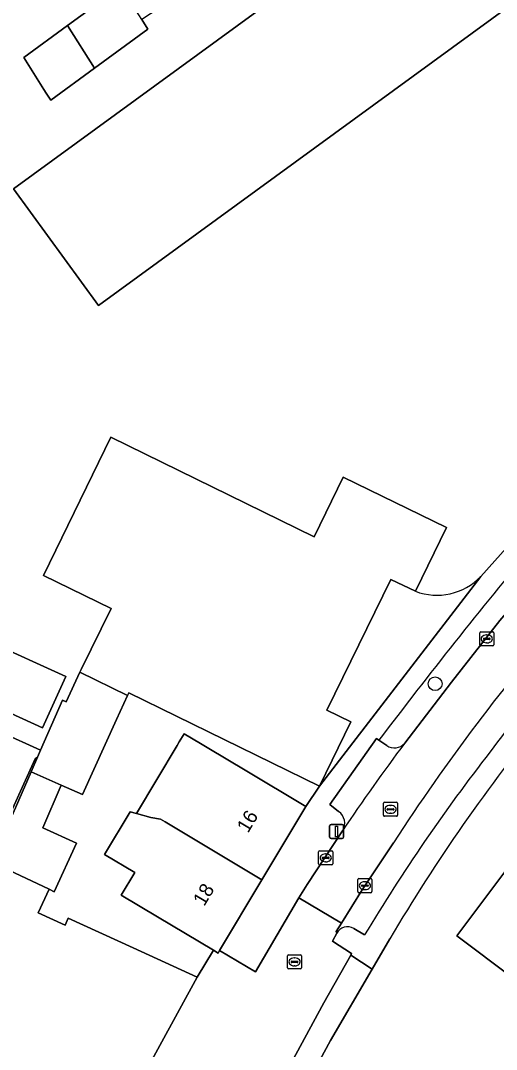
# Model space of a CAD drawing. Extents: x 161881 to 162523, y 381678 to 382381.
# Drawn here: x 162276 to 162309.8, y 381824.1 to 381897.2 of the extents above; entities that cross this region are included whole.
import ezdxf

# ---------------------------------------------------------------- set-up
doc = ezdxf.new("R2010")
doc.units = 0
for name, color, linetype in [('IMGEO_Boom', 7, 'Continuous'), ('IMGEO_Erf', 7, 'Continuous'), ('IMGEO_Groenvoorziening', 7, 'Continuous'), ('IMGEO_Kolk', 7, 'Continuous'), ('IMGEO_Lichtmast', 7, 'Continuous'), ('IMGEO_Muur', 7, 'Continuous'), ('IMGEO_Pand', 7, 'Continuous'), ('IMGEO_Pand_nummerreeks', 7, 'Continuous'), ('IMGEO_Parkeervlak_open', 7, 'Continuous'), ('IMGEO_Rijbaan_lokaal_open', 7, 'Continuous'), ('IMGEO_Rioolput', 7, 'Continuous'), ('IMGEO_Voetpad_open', 7, 'Continuous')]:
    doc.layers.add(name, color=color, linetype=linetype)

msp = doc.modelspace()

# ---------------------------------------------------------------- linework, layer by layer
at = {"layer": 'IMGEO_Boom'}
msp.add_circle((162305.454, 381850.04), 0.489, dxfattribs=at)
at = {"layer": 'IMGEO_Erf'}
for points in [[(162275.507, 381885.197), (162313.123, 381912.663)], [(162308.695, 381857.661), (162317.651, 381867.68), (162320.093, 381870.515), (162317.508, 381873.557), (162311.416, 381880.988), (162315.774, 381884.648), (162315.994, 381884.379), (162316.488, 381884.836), (162316.601, 381884.938), (162316.382, 381885.179), (162318.764, 381887.154), (162318.965, 381886.995), (162319.543, 381887.466), (162319.343, 381887.695), (162320.508, 381888.575), (162315.645, 381894.334), (162318.477, 381896.725), (162315.068, 381901.394), (162281.55, 381876.921), (162275.507, 381885.197)], [(162274.603, 381846.604), (162277.429, 381845.321), (162278.983, 381848.869), (162279.241, 381848.751), (162280.22, 381850.86), (162280.31, 381851.043), (162282.429, 381855.385), (162277.623, 381857.736), (162282.425, 381867.55), (162296.856, 381860.49), (162298.927, 381864.723), (162306.263, 381861.133), (162304.05, 381856.609)], [(162273.937, 381837.352), (162276.749, 381843.77), (162277.212, 381844.825), (162277.045, 381844.695), (162273.678, 381837.331)], [(162302.232, 381831.916), (162300.971, 381829.755), (162298.019, 381824.698), (162294.798, 381818.75)]]:
    msp.add_lwpolyline(points, dxfattribs=at)
for points in [[(162278.151, 381891.503), (162277.827, 381892.015), (162277.662, 381892.277), (162276.229, 381894.543), (162279.326, 381896.811), (162283.128, 381899.595), (162282.478, 381900.624), (162284.502, 381901.961), (162284.785, 381902.148), (162286.788, 381903.471), (162286.974, 381903.176), (162288.926, 381900.089), (162284.616, 381897.241), (162285.049, 381896.555), (162281.247, 381893.771)], [(162279.221, 381850.549), (162277.559, 381846.911), (162272.006, 381849.436), (162273.668, 381853.074)], [(162324.194, 381841.527), (162320.657, 381836.81), (162323.58, 381834.6), (162320.051, 381829.895), (162317.092, 381832.114), (162313.465, 381827.278), (162310.999, 381829.127), (162306.999, 381832.127), (162310.626, 381836.963), (162314.163, 381841.68), (162317.701, 381846.396), (162321.328, 381851.233), (162325.328, 381848.233), (162327.821, 381846.363)], [(162287.133, 381845.652), (162287.282, 381845.902), (162287.63, 381846.483), (162288.786, 381845.792), (162289.388, 381845.432), (162291.968, 381843.889), (162296.259, 381841.323), (162297.241, 381842.76), (162283.693, 381849.389), (162283.607, 381849.201), (162282.828, 381847.495), (162280.399, 381842.176), (162278.877, 381842.841), (162277.585, 381839.797), (162279.968, 381838.708), (162278.395, 381835.263), (162278.028, 381835.435), (162277.263, 381833.76), (162279.176, 381832.887), (162279.396, 381833.371), (162283.992, 381831.27), (162288.539, 381829.192), (162289.703, 381831.102), (162285.739, 381833.472), (162283.159, 381835.015), (162284.124, 381836.63), (162281.972, 381837.916), (162283.782, 381840.944), (162284.241, 381840.816)]]:
    msp.add_lwpolyline(points, close=True, dxfattribs=at)
for centre, radius, start, end in [((162305.575, 381860.656), 4.325, 249.35475, 316.1674), ((162413.302, 381766.264), 129.022, 140.83, 149.413)]:
    msp.add_arc(centre, radius, start, end, dxfattribs=at)
at = {"layer": 'IMGEO_Groenvoorziening'}
for points in [[(162303.292, 381845.82), (162306.611, 381850.151), (162310.057, 381854.543), (162313.959, 381859.114), (162317.095, 381862.667), (162320.649, 381866.638)], [(162301.461, 381846.023), (162302.017, 381845.655)]]:
    msp.add_lwpolyline(points, dxfattribs=at)
msp.add_lwpolyline([(162300.971, 381829.755), (162299.458, 381830.76), (162297.547, 381827.377), (162294.938, 381822.561), (162294.387, 381822.839), (162294.119, 381822.297), (162293.749, 381821.597), (162294.258, 381821.315), (162293.302, 381819.526), (162294.798, 381818.75), (162298.019, 381824.698)], close=True, dxfattribs=at)
for centre, radius, start, end in [((162591.617, 381627.062), 363.503, 140.18045, 142.96062), ((162302.567, 381846.417), 0.94, 234.21404, 320.53349)]:
    msp.add_arc(centre, radius, start, end, dxfattribs=at)
at = {"layer": 'IMGEO_Kolk'}
for p, q in [((162308.622, 381852.803), (162308.622, 381853.655)), ((162308.697, 381853.729), (162309.549, 381853.729)), ((162309.623, 381853.655), (162309.623, 381852.803)), ((162308.881, 381853.223), (162308.881, 381853.235)), ((162309.319, 381853.186), (162308.921, 381853.186)), ((162308.924, 381853.272), (162309.322, 381853.272)), ((162309.133, 381852.949), (162309.108, 381852.949)), ((162309.11, 381853.509), (162309.135, 381853.509)), ((162309.365, 381853.235), (162309.365, 381853.223)), ((162309.549, 381852.729), (162308.697, 381852.729)), ((162297.179, 381837.241), (162297.179, 381838.093)), ((162297.254, 381838.167), (162298.106, 381838.167)), ((162297.438, 381837.661), (162297.438, 381837.673)), ((162297.876, 381837.624), (162297.478, 381837.624)), ((162297.481, 381837.71), (162297.879, 381837.71)), ((162297.667, 381837.947), (162297.692, 381837.947)), ((162297.922, 381837.673), (162297.922, 381837.661)), ((162298.18, 381838.093), (162298.18, 381837.241)), ((162298.106, 381837.167), (162297.254, 381837.167)), ((162297.69, 381837.387), (162297.665, 381837.387)), ((162299.966, 381835.267), (162299.966, 381836.119)), ((162300.041, 381836.193), (162300.893, 381836.193)), ((162300.967, 381836.119), (162300.967, 381835.267)), ((162300.225, 381835.687), (162300.225, 381835.699)), ((162300.663, 381835.65), (162300.265, 381835.65)), ((162300.268, 381835.736), (162300.666, 381835.736)), ((162300.477, 381835.413), (162300.452, 381835.413)), ((162300.454, 381835.973), (162300.479, 381835.973)), ((162300.709, 381835.699), (162300.709, 381835.687)), ((162300.893, 381835.193), (162300.041, 381835.193)), ((162294.966, 381829.85), (162294.966, 381830.702)), ((162295.041, 381830.776), (162295.893, 381830.776)), ((162295.225, 381830.27), (162295.225, 381830.282)), ((162295.268, 381830.319), (162295.666, 381830.319)), ((162295.454, 381830.556), (162295.479, 381830.556)), ((162295.709, 381830.282), (162295.709, 381830.27)), ((162295.967, 381830.702), (162295.967, 381829.85)), ((162295.893, 381829.776), (162295.041, 381829.776)), ((162295.663, 381830.233), (162295.265, 381830.233)), ((162295.477, 381829.996), (162295.452, 381829.996))]:
    msp.add_line(p, q, dxfattribs=at)
for points in [[(162308.622, 381852.803), (162308.622, 381853.655)], [(162308.697, 381853.729), (162309.549, 381853.729)], [(162309.623, 381853.655), (162309.623, 381852.803)], [(162309.549, 381852.729), (162308.697, 381852.729)], [(162297.179, 381837.241), (162297.179, 381838.093)], [(162297.254, 381838.167), (162298.106, 381838.167)], [(162298.18, 381838.093), (162298.18, 381837.241)], [(162298.106, 381837.167), (162297.254, 381837.167)], [(162299.966, 381835.267), (162299.966, 381836.119)], [(162300.041, 381836.193), (162300.893, 381836.193)], [(162300.967, 381836.119), (162300.967, 381835.267)], [(162300.893, 381835.193), (162300.041, 381835.193)], [(162294.966, 381829.85), (162294.966, 381830.702)], [(162295.041, 381830.776), (162295.893, 381830.776)], [(162295.967, 381830.702), (162295.967, 381829.85)], [(162295.893, 381829.776), (162295.041, 381829.776)]]:
    msp.add_lwpolyline(points, dxfattribs=at)
for centre, radius, start, end in [((162308.699, 381853.653), 0.0765, 91.55205, 178.44795), ((162308.699, 381853.653), 0.0765, 91.55205, 178.44795), ((162309.547, 381853.653), 0.0765, 1.55205, 88.44795), ((162309.547, 381853.653), 0.0765, 1.55205, 88.44795), ((162308.921, 381853.232), 0.0403, 85.87752, 175.75265), ((162308.918, 381853.222), 0.0366, 178.93798, 274.71019), ((162309.322, 381853.229), 0.043, 264.86636, 352.45326), ((162309.326, 381853.234), 0.0386, 1.73085, 96.63898), ((162308.699, 381852.805), 0.0765, 181.55205, 268.44795), ((162308.699, 381852.805), 0.0765, 181.55205, 268.44795), ((162309.547, 381852.805), 0.0765, 271.55205, 358.44795), ((162309.547, 381852.805), 0.0765, 271.55205, 358.44795), ((162297.256, 381838.091), 0.0765, 91.55205, 178.44795), ((162297.256, 381838.091), 0.0765, 91.55205, 178.44795), ((162297.478, 381837.67), 0.0403, 85.87752, 175.75265), ((162297.475, 381837.66), 0.0366, 178.93798, 274.71019), ((162297.879, 381837.667), 0.043, 264.86636, 352.45326), ((162297.883, 381837.672), 0.0386, 1.73085, 96.63898), ((162298.104, 381838.091), 0.0765, 1.55205, 88.44795), ((162298.104, 381838.091), 0.0765, 1.55205, 88.44795), ((162297.256, 381837.243), 0.0765, 181.55205, 268.44795), ((162297.256, 381837.243), 0.0765, 181.55205, 268.44795), ((162298.104, 381837.243), 0.0765, 271.55205, 358.44795), ((162298.104, 381837.243), 0.0765, 271.55205, 358.44795), ((162300.043, 381836.117), 0.0765, 91.55205, 178.44795), ((162300.043, 381836.117), 0.0765, 91.55205, 178.44795), ((162300.891, 381836.117), 0.0765, 1.55205, 88.44795), ((162300.891, 381836.117), 0.0765, 1.55205, 88.44795), ((162300.265, 381835.696), 0.0403, 85.87752, 175.75265), ((162300.262, 381835.686), 0.0366, 178.93798, 274.71019), ((162300.666, 381835.693), 0.043, 264.86636, 352.45326), ((162300.67, 381835.698), 0.0386, 1.73085, 96.63898), ((162300.043, 381835.269), 0.0765, 181.55205, 268.44795), ((162300.043, 381835.269), 0.0765, 181.55205, 268.44795), ((162300.891, 381835.269), 0.0765, 271.55205, 358.44795), ((162300.891, 381835.269), 0.0765, 271.55205, 358.44795), ((162295.043, 381830.7), 0.0765, 91.55205, 178.44795), ((162295.043, 381830.7), 0.0765, 91.55205, 178.44795), ((162295.265, 381830.279), 0.0403, 85.87752, 175.75265), ((162295.262, 381830.269), 0.0366, 178.93798, 274.71019), ((162295.666, 381830.276), 0.043, 264.86636, 352.45326), ((162295.67, 381830.281), 0.0386, 1.73085, 96.63898), ((162295.891, 381830.7), 0.0765, 1.55205, 88.44795), ((162295.891, 381830.7), 0.0765, 1.55205, 88.44795), ((162295.043, 381829.852), 0.0765, 181.55205, 268.44795), ((162295.043, 381829.852), 0.0765, 181.55205, 268.44795), ((162295.891, 381829.852), 0.0765, 271.55205, 358.44795), ((162295.891, 381829.852), 0.0765, 271.55205, 358.44795)]:
    msp.add_arc(centre, radius, start, end, dxfattribs=at)
for centre, major_axis, ratio, start_param, end_param in [((162309.109, 381853.229), (-0.387, 0.002), 0.722429, 4.712389, 7.853982), ((162309.134, 381853.229), (-0.39, 0.002), 0.717154, 1.570796, 4.712389), ((162297.666, 381837.667), (-0.387, 0.002), 0.722429, 4.712389, 7.853982), ((162297.691, 381837.667), (-0.39, 0.002), 0.717154, 1.570796, 4.712389), ((162300.453, 381835.693), (-0.387, 0.002), 0.722429, 4.712389, 7.853982), ((162300.478, 381835.693), (-0.39, 0.002), 0.717154, 1.570796, 4.712389), ((162295.453, 381830.276), (-0.387, 0.002), 0.722429, 4.712389, 7.853982), ((162295.478, 381830.276), (-0.39, 0.002), 0.717154, 1.570796, 4.712389)]:
    msp.add_ellipse(centre, major_axis=major_axis, ratio=ratio, start_param=start_param, end_param=end_param, dxfattribs=at)
at = {"layer": 'IMGEO_Lichtmast'}
for p, q in [((162297.958, 381839.144), (162297.958, 381839.944)), ((162297.958, 381839.944), (162297.958, 381839.144)), ((162298.058, 381840.044), (162298.848, 381840.044)), ((162298.848, 381840.044), (162298.058, 381840.044)), ((162298.948, 381839.944), (162298.948, 381839.144)), ((162298.948, 381839.144), (162298.948, 381839.944)), ((162298.848, 381839.044), (162298.058, 381839.044)), ((162298.058, 381839.044), (162298.848, 381839.044))]:
    msp.add_line(p, q, dxfattribs=at)
msp.add_lwpolyline([(162298.378, 381839.919), (162298.528, 381839.919), (162298.528, 381839.169), (162298.378, 381839.169), (162298.378, 381839.919)], dxfattribs=at)
for centre, start, end in [((162298.058, 381839.944), 90, 180), ((162298.058, 381839.944), 90, 180), ((162298.848, 381839.944), 0, 90), ((162298.848, 381839.944), 360, 90), ((162298.058, 381839.144), 180, 270), ((162298.058, 381839.144), 180, 270), ((162298.848, 381839.144), 270, 0), ((162298.848, 381839.144), 270, 0)]:
    msp.add_arc(centre, 0.1, start, end, dxfattribs=at)
at = {"layer": 'IMGEO_Muur'}
msp.add_lwpolyline([(162302.232, 381831.916), (162300.971, 381829.755), (162298.019, 381824.698), (162294.798, 381818.75), (162293.862, 381817.021), (162292.645, 381814.351), (162293.291, 381814.057)], dxfattribs=at)
at = {"layer": 'IMGEO_Pand'}
for points in [[(162315.068, 381901.394), (162318.477, 381896.725), (162315.645, 381894.334), (162320.508, 381888.575), (162331.126, 381897.517), (162324.457, 381905.392), (162322.762, 381907.393), (162318.985, 381904.635), (162313.123, 381912.663), (162275.507, 381885.197), (162281.55, 381876.921)], [(162284.616, 381897.241), (162283.128, 381899.595), (162279.326, 381896.811), (162281.247, 381893.771), (162285.049, 381896.555)], [(162281.247, 381893.771), (162279.326, 381896.811), (162276.229, 381894.543), (162277.662, 381892.277), (162277.827, 381892.015), (162278.151, 381891.503)], [(162280.22, 381850.86), (162283.607, 381849.201), (162283.693, 381849.389), (162297.241, 381842.76), (162299.476, 381847.329), (162297.77, 381848.164), (162302.316, 381857.457), (162304.05, 381856.609), (162306.263, 381861.133), (162298.927, 381864.723), (162296.856, 381860.49), (162282.425, 381867.55), (162277.623, 381857.736), (162282.429, 381855.385), (162280.31, 381851.043)], [(162277.559, 381846.911), (162279.221, 381850.549), (162273.668, 381853.074), (162272.006, 381849.436)], [(162282.828, 381847.495), (162283.607, 381849.201), (162280.22, 381850.86), (162279.241, 381848.751), (162278.983, 381848.869), (162277.429, 381845.321), (162277.212, 381844.825), (162276.749, 381843.77), (162278.877, 381842.841), (162280.399, 381842.176)], [(162277.212, 381844.825), (162277.429, 381845.321), (162274.603, 381846.604), (162273.63, 381846.161), (162270.607, 381839.556), (162270.987, 381838.554), (162271.241, 381838.439), (162273.678, 381837.331), (162277.045, 381844.695)], [(162296.259, 381841.323), (162291.968, 381843.889), (162289.388, 381845.432), (162288.786, 381845.792), (162287.63, 381846.483), (162287.282, 381845.902), (162287.133, 381845.652), (162284.241, 381840.816), (162285.262, 381840.532), (162285.941, 381840.421), (162286.273, 381840.223), (162293.145, 381836.115)], [(162278.877, 381842.841), (162276.749, 381843.77), (162273.937, 381837.352), (162278.028, 381835.435), (162278.395, 381835.263), (162279.968, 381838.708), (162277.585, 381839.797)], [(162293.145, 381836.115), (162286.273, 381840.223), (162285.941, 381840.421), (162285.262, 381840.532), (162284.241, 381840.816), (162283.782, 381840.944), (162281.972, 381837.916), (162284.124, 381836.63), (162283.159, 381835.015), (162285.739, 381833.472), (162289.703, 381831.102), (162290.03, 381830.906), (162290.13, 381831.074)], [(162284.507, 381821.787), (162288.539, 381829.192), (162283.992, 381831.27), (162279.396, 381833.371), (162279.176, 381832.887), (162277.263, 381833.76), (162278.028, 381835.435), (162273.937, 381837.352), (162273.499, 381836.351), (162273.867, 381836.183), (162272.302, 381832.759), (162271.987, 381832.903), (162269.766, 381827.834), (162270.107, 381827.678), (162269.172, 381825.632), (162274.569, 381822.855), (162270.405, 381813.427), (162267.49, 381807.052), (162275.953, 381803.185), (162276.093, 381803.496), (162283.439, 381819.827)], [(162310.626, 381836.963), (162306.999, 381832.127), (162310.999, 381829.127), (162313.465, 381827.278), (162317.092, 381832.114)]]:
    msp.add_lwpolyline(points, close=True, dxfattribs=at)
at = {"layer": 'IMGEO_Parkeervlak_open'}
for points in [[(162302.017, 381845.655), (162301.461, 381846.023), (162301.282, 381846.141), (162297.963, 381841.469), (162298.598, 381840.973)], [(162302.496, 381838.745), (162300.266, 381835.391), (162298.801, 381833.037), (162298.421, 381832.426), (162298.469, 381832.313)], [(162299.669, 381832.644), (162300.442, 381832.187)]]:
    msp.add_lwpolyline(points, dxfattribs=at)
for centre, radius, start, end in [((162415.221, 381766.452), 131.939, 137.15809, 143.35927), ((162424.966, 381759.231), 146.019, 138.91675, 147.00635), ((162409.25, 381766.07), 132.616, 143.03256, 146.33174), ((162302.567, 381846.417), 0.94, 234.21404, 320.53349), ((162414.424, 381763.64), 133.006, 142.18231, 148.97808), ((162297.993, 381840.131), 1.037, 328.5773, 54.31331), ((162299.221, 381831.927), 0.845, 57.98862, 152.85265)]:
    msp.add_arc(centre, radius, start, end, dxfattribs=at)
at = {"layer": 'IMGEO_Rijbaan_lokaal_open'}
for points in [[(162314.904, 381855.188), (162316.997, 381857.442), (162317.714, 381858.155), (162320.231, 381860.917), (162323.422, 381864.435), (162320.649, 381866.638), (162317.095, 381862.667), (162313.959, 381859.114), (162310.057, 381854.543), (162306.611, 381850.151), (162303.292, 381845.82)], [(162298.878, 381839.59), (162296.354, 381835.769), (162295.774, 381834.818), (162298.801, 381833.037), (162300.266, 381835.391), (162302.496, 381838.745)], [(162294.938, 381822.561), (162297.547, 381827.377), (162299.458, 381830.76), (162299.515, 381830.861), (162298.167, 381831.758), (162298.469, 381832.313), (162298.421, 381832.426), (162298.801, 381833.037), (162295.774, 381834.818), (162292.698, 381829.565), (162290.13, 381831.074), (162290.03, 381830.906), (162289.703, 381831.102), (162288.539, 381829.192), (162284.507, 381821.787)]]:
    msp.add_lwpolyline(points, dxfattribs=at)
for centre, radius, start, end in [((162424.966, 381759.231), 146.019, 138.91675, 147.00635), ((162409.25, 381766.07), 132.616, 143.03256, 146.33174)]:
    msp.add_arc(centre, radius, start, end, dxfattribs=at)
at = {"layer": 'IMGEO_Rioolput'}
for p, q in [((162301.787, 381840.694), (162301.787, 381841.546)), ((162301.862, 381841.62), (162302.714, 381841.62)), ((162302.275, 381841.4), (162302.3, 381841.4)), ((162302.788, 381841.546), (162302.788, 381840.694)), ((162302.714, 381840.62), (162301.862, 381840.62)), ((162302.046, 381841.114), (162302.046, 381841.126)), ((162302.484, 381841.077), (162302.086, 381841.077)), ((162302.089, 381841.163), (162302.487, 381841.163)), ((162302.298, 381840.84), (162302.273, 381840.84)), ((162302.53, 381841.126), (162302.53, 381841.114))]:
    msp.add_line(p, q, dxfattribs=at)
for points in [[(162301.787, 381840.694), (162301.787, 381841.546)], [(162301.862, 381841.62), (162302.714, 381841.62)], [(162302.788, 381841.546), (162302.788, 381840.694)], [(162302.714, 381840.62), (162301.862, 381840.62)]]:
    msp.add_lwpolyline(points, dxfattribs=at)
for centre, radius, start, end in [((162301.864, 381841.544), 0.0765, 91.55205, 178.44795), ((162301.864, 381841.544), 0.0765, 91.55205, 178.44795), ((162302.712, 381841.544), 0.0765, 1.55205, 88.44795), ((162302.712, 381841.544), 0.0765, 1.55205, 88.44795), ((162301.864, 381840.696), 0.0765, 181.55205, 268.44795), ((162301.864, 381840.696), 0.0765, 181.55205, 268.44795), ((162302.086, 381841.123), 0.0403, 85.87752, 175.75265), ((162302.083, 381841.113), 0.0366, 178.93798, 274.71019), ((162302.487, 381841.12), 0.043, 264.86636, 352.45326), ((162302.491, 381841.125), 0.0386, 1.73085, 96.63898), ((162302.712, 381840.696), 0.0765, 271.55205, 358.44795), ((162302.712, 381840.696), 0.0765, 271.55205, 358.44795)]:
    msp.add_arc(centre, radius, start, end, dxfattribs=at)
for centre, major_axis, ratio, start_param, end_param in [((162302.274, 381841.12), (-0.387, 0.002), 0.722429, 4.712389, 7.853982), ((162302.299, 381841.12), (-0.39, 0.002), 0.717154, 1.570796, 4.712389)]:
    msp.add_ellipse(centre, major_axis=major_axis, ratio=ratio, start_param=start_param, end_param=end_param, dxfattribs=at)
at = {"layer": 'IMGEO_Voetpad_open'}
for points in [[(162323.967, 381873.987), (162320.411, 381871.008), (162318.587, 381873.075), (162318.649, 381873.357), (162312.385, 381880.712), (162315.826, 381883.619), (162316.82, 381884.434), (162316.488, 381884.836), (162315.994, 381884.379), (162315.774, 381884.648), (162311.416, 381880.988), (162317.508, 381873.557), (162320.093, 381870.515), (162317.651, 381867.68), (162308.695, 381857.661), (162297.241, 381842.76), (162296.259, 381841.323), (162293.145, 381836.115), (162290.13, 381831.074), (162292.698, 381829.565), (162295.774, 381834.818), (162296.354, 381835.769), (162298.878, 381839.59)], [(162304.05, 381856.609), (162302.316, 381857.457), (162297.77, 381848.164), (162299.476, 381847.329), (162297.241, 381842.76), (162308.695, 381857.661)], [(162298.598, 381840.973), (162297.963, 381841.469), (162301.282, 381846.141), (162301.461, 381846.023)], [(162300.442, 381832.187), (162299.669, 381832.644)], [(162298.469, 381832.313), (162298.167, 381831.758), (162299.515, 381830.861), (162299.458, 381830.76), (162300.971, 381829.755), (162302.232, 381831.916)]]:
    msp.add_lwpolyline(points, dxfattribs=at)
for centre, radius, start, end in [((162591.617, 381627.062), 363.503, 140.18045, 142.96062), ((162305.575, 381860.656), 4.325, 249.35475, 316.1674), ((162415.221, 381766.452), 131.939, 137.15809, 143.35927), ((162413.302, 381766.264), 129.022, 140.83, 149.413), ((162414.424, 381763.64), 133.006, 142.18231, 148.97808), ((162297.993, 381840.131), 1.037, 328.5773, 54.31331), ((162299.221, 381831.927), 0.845, 57.98862, 152.85265)]:
    msp.add_arc(centre, radius, start, end, dxfattribs=at)

# ---------------------------------------------------------------- texts
at = {"layer": 'IMGEO_Pand_nummerreeks'}
for s, p in [('16', (162292.162, 381839.381)), ('18', (162289.048, 381834.175))]:
    msp.add_text(s, height=1, rotation=59.12351, dxfattribs=at).set_placement(p)

doc.saveas('drawing.dxf')
